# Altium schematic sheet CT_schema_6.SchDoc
size 405 x 220 mm
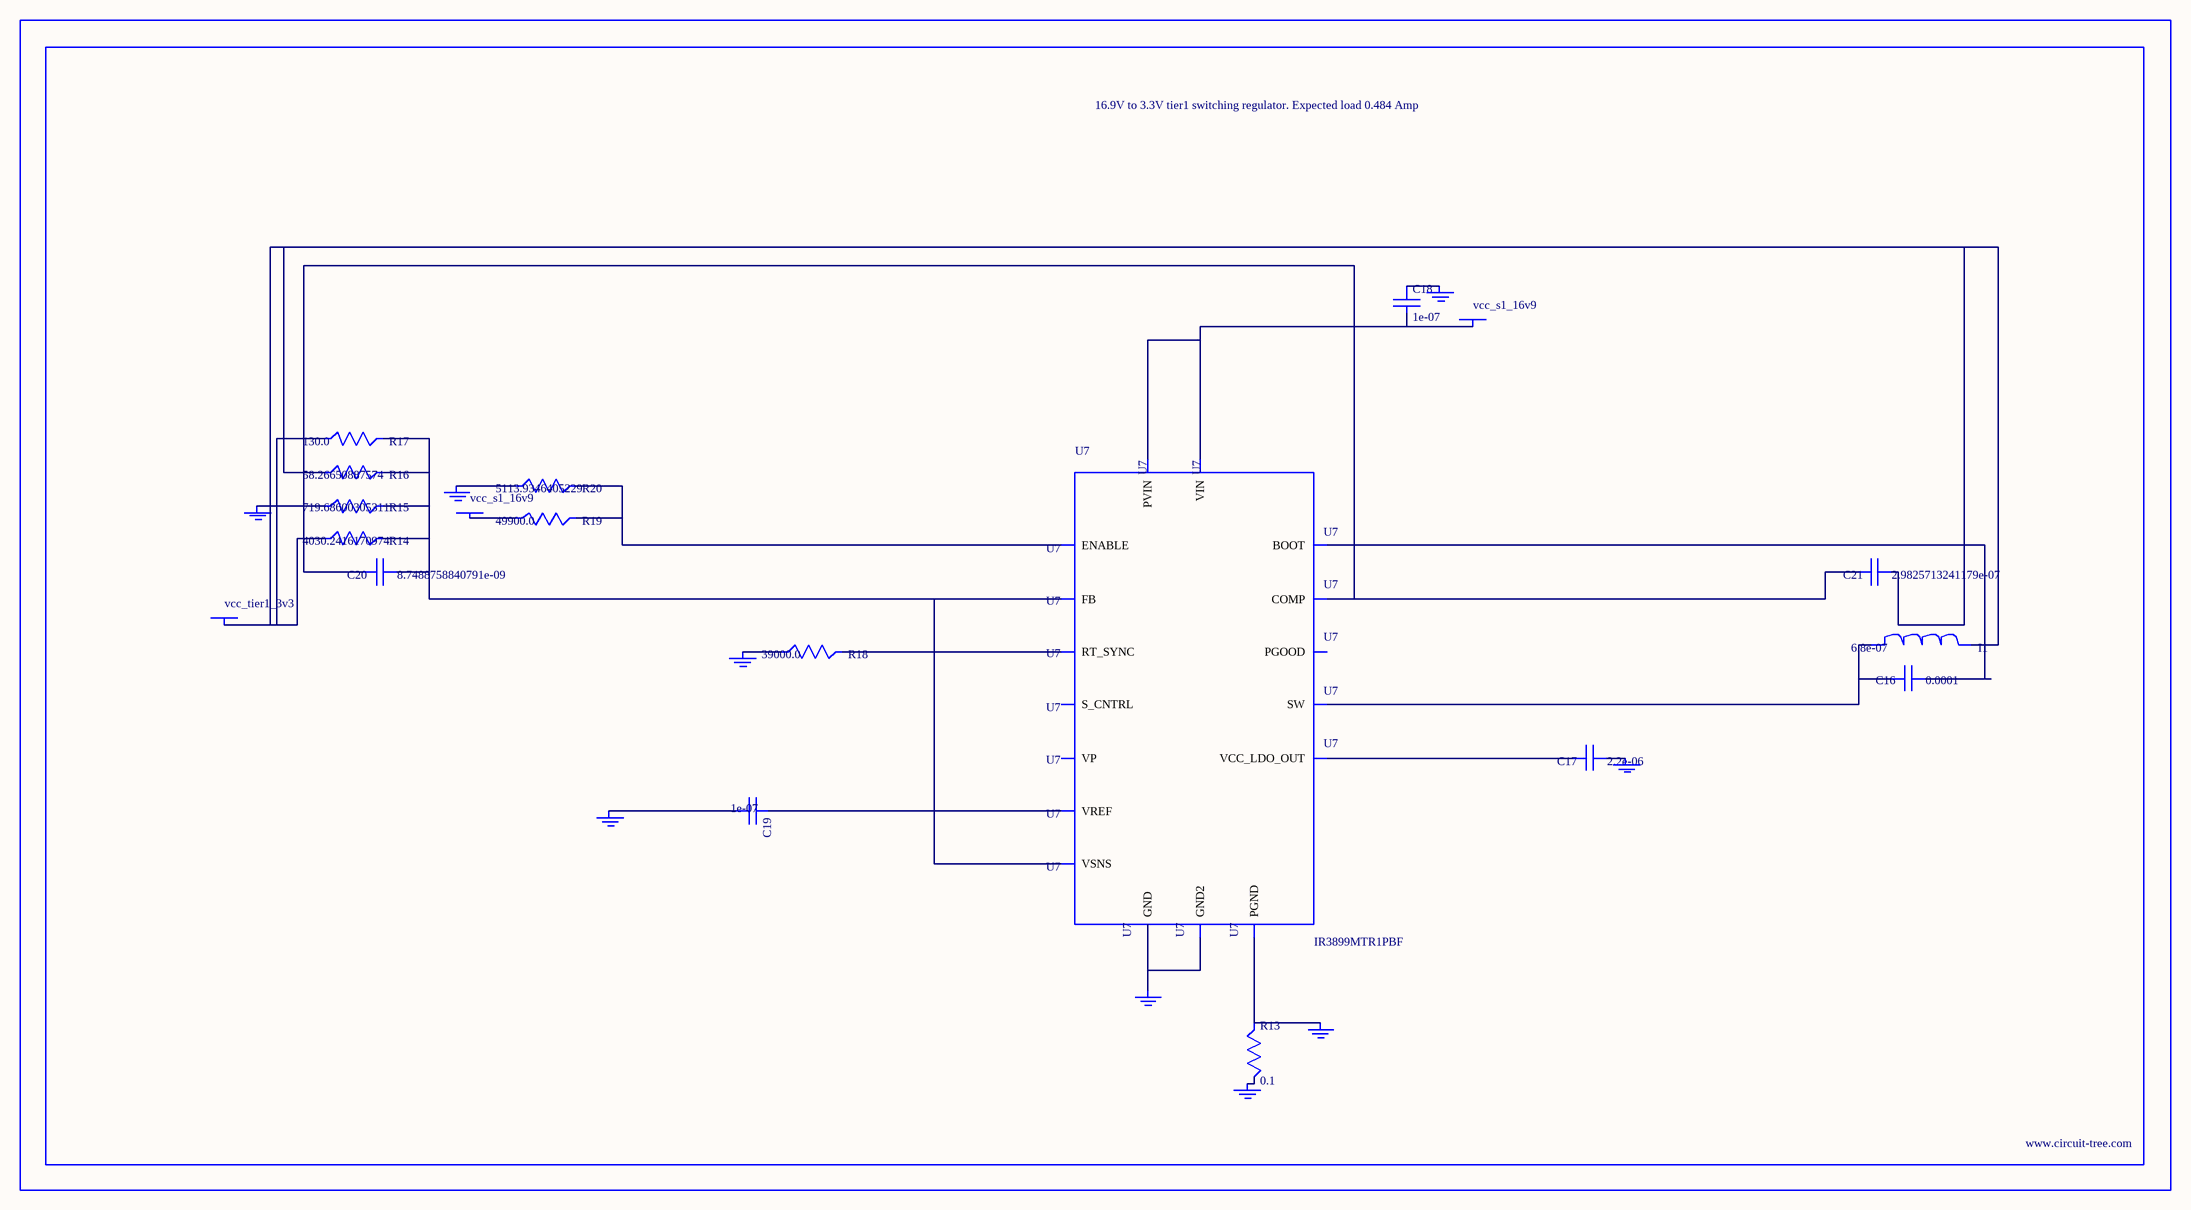
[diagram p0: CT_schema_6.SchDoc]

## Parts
BORDER5  (no value)
C16  0.0001  [C1210]
C17  2.2e-06  [C0603]
C18  1e-07  [C0402]
C19  1e-07  [C0402]
C20  8.7488758840791e-09  [R0603]
C21  2.9825713241179e-07  [R0603]
GND_INSTANCE_5_0  (no value)
GND_INSTANCE_5_1  (no value)
GND_INSTANCE_5_2  (no value)
GND_INSTANCE_5_3  (no value)
GND_INSTANCE_5_4  (no value)
GND_INSTANCE_5_5  (no value)
GND_INSTANCE_5_6  (no value)
GND_INSTANCE_5_7  (no value)
GND_INSTANCE_5_8  (no value)
I1  6.8e-07  [IND25X25CZ]
POWER_INSTANCE_5_0  vcc_s1_16v9
POWER_INSTANCE_5_1  vcc_s1_16v9
POWER_INSTANCE_5_2  vcc_tier1_3v3
R13  0.1  [R0603]
R14  4030.2416170974  [R0603]
R15  719.68600305311  [R0603]
R16  58.26650887574  [R0603]
R17  130.0  [R0603]
R18  39000.0  [R0603]
R19  49900.0  [R0603]
R20  5113.9346405229  [R0603]
U7  IR3899MTR1PBF  [IR3899MTR1PBF]

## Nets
NetC16_1: C16.1 U7.14(BOOT)
NetC16_2: C16.2 I1.1 U7.12(SW)
NetC17_1: C17.1 GND_INSTANCE_5_4.0(GND)
NetC17_2: C17.2 U7.10(VCC_LDO_OUT)
NetC18_1: C18.1 GND_INSTANCE_5_3.0(GND)
NetC18_2: C18.2 POWER_INSTANCE_5_0.0(PWR) U7.9(VIN) U7.13(PVIN)
NetC19_1: C19.1 U7.2(VREF)
NetC19_2: C19.2 GND_INSTANCE_5_1.0(GND)
NetC20_1: C20.1 R14.2 R15.2 R16.2 R17.2 U7.1(FB) U7.8(VSNS)
NetC20_2: C20.2 C21.2 U7.3(COMP)
NetC21_1: C21.1 I1.2 POWER_INSTANCE_5_2.0(PWR) R14.1 R16.1 R17.1
NetGND_INSTANCE_5_0_0: GND_INSTANCE_5_0.0(GND) R15.1
NetGND_INSTANCE_5_2_0: GND_INSTANCE_5_2.0(GND) R18.1
NetGND_INSTANCE_5_5_0: GND_INSTANCE_5_5.0(GND) R13.2
NetGND_INSTANCE_5_6_0: GND_INSTANCE_5_6.0(GND) R13.1 U7.11(PGND)
NetGND_INSTANCE_5_7_0: GND_INSTANCE_5_7.0(GND) R20.1
NetGND_INSTANCE_5_8_0: GND_INSTANCE_5_8.0(GND) U7.4(GND) U7.17(GND2)
NetPOWER_INSTANCE_5_1_0: POWER_INSTANCE_5_1.0(PWR) R19.1
NetR18_2: R18.2 U7.5(RT_SYNC)
NetR19_2: R19.2 R20.2 U7.15(ENABLE)

Not connected (* = marked no-connect by the designer): U7 6(S_CNTRL) 7(PGOOD) 16(VP)

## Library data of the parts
BORDER5 = BORDER_PAGE5
C16 = GRM32ER61A107ME20L
C17 = C0603C225K8RACTU
C18 C19 = C0402C104K3RACTU
C20 = C20
C21 = C21
GND_INSTANCE_5_0-GND_INSTANCE_5_8 = GND
I1 = IHLP2525CZERR68M01
POWER_INSTANCE_5_0-POWER_INSTANCE_5_2 = PWR
R13 = ERJ-3RSFR10V
R14 = R14
R15 = R15
R16 = R16
R17 = RC0603JR-07130RL
R18 = RC0603JR-0739KL
R19 = RC0603FR-0749K9
R20 = R20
